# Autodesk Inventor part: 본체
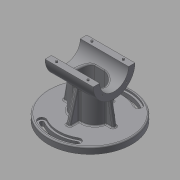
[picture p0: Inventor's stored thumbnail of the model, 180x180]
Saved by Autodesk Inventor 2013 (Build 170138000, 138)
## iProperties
Created: 2015-12
Part Number: 본체
Material: 일반
Document SubType Name: Modeling
Designer: mduedu
Density: 2.71 g/cm^3
Author: mduedu
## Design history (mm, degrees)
sketch "스케치1"
  geometry: C1 r 65 at (0, 0); 1 further point
  constraints: 1 centre point, 1 coincident
  dimensions: "d124" = 130 diameter of C1
extrude "돌출1" new body sketch "스케치1" distance "d3" = 10; taper "d4" = 0 deg
sketch "스케치2"
  geometry: C1 r 32.5 at (80, 0); 1 further point
  constraints: 1 centre point, 1 horizontal alignment
  dimensions: "d5" = 65 diameter of C1; "d125" = 80 distance of C1.centre point (0, 0)
extrude "돌출2" join sketch "스케치2" stored distance "d7" = 75; taper "d8" = 0 deg
sketch "스케치3"
  geometry: L1 (-27.5, -20)-(27.5, -20); L2 (27.5, -20)-(27.5, 20); L3 (27.5, 20)-(-27.5, 20); L4 (-27.5, 20)-(-27.5, -20); L5 (-27.5, -20)-(27.5, 20); L6 (27.5, -20)-(-27.5, 20); 1 further point
  constraints: 12 end point, 2 midpoint, 2 parallel, 1 horizontal, 1 perpendicular
  dimensions: "d9" = 55 distance of L2.end L3.end; "d11" = 40 distance of L1.end L2.end
extrude "돌출3" new body sketch "스케치3" stored distance "d12" = 75; taper "d13" = 0 deg
fillet "모깎기1"
fillet "모깎기2"
feature "결합1"
  node "솔리드2"
sketch "스케치4"
  geometry: L1 (-37.5, 47.5)-(37.5, 47.5) reference; L2 (32.5, 47.5)-(39.112, 10); L3 (37.5, 47.5)-(37.5, 112.5) reference; L4 (65, 10)-(-65, 10) reference; 1 further point
  constraints: 2 end point, 2 point on line
  dimensions: "d15" = 5 distance from line of L2.start L3; "d126" = 80 deg angle of L2 L1
sketch "스케치5"
  geometry: L1 (10, 35)-(56.569, 22.522); L2 (10, -65)-(10, 65) reference; L3 (10, 20)-(54.383, 20) reference; A1 r 32.5 centre (80, 0) between (56.569, 22.522) and (54.383, 20) reference; 1 further point
  constraints: 2 end point, 1 point on circle, 1 point on line
  dimensions: "d127" = 75 deg angle of L1 L2; "d128" = 15 distance of L1.start L3.start
feature "리브1" dims "d19" = 1, "d20" = 6, "d21" = 0, "d22" = 0, "d23" = 1, "d24" = 1
feature "리브2" dims "d25" = 1, "d26" = 6, "d27" = 0, "d28" = 0, "d29" = 1, "d30" = 1
fillet "모깎기4" dims "d31" = 2
fillet "모깎기5" dims "d32" = 2
fillet "모깎기6" dims "d33" = 2
fillet "모깎기7" dims "d41" = 2
hole "구멍2" diameter "d44" = 45; stored, may be unused: countersink angle "d48" = 90 deg, drill point angle "d50" = 118 deg; dims "d42" = 10, "d43" = 10, "d45" = 6, "d46" = 4, "d47" = 2, "d49" = 8
sketch "스케치7" dims "d52" = 26.5
  geometry: L1 (0, 0)-(32.5, 0); L2 (0, 0)-(22.981, 22.981); A1 r 32.5 centre (0, 0) between (32.5, 0) and (22.981, 22.981) reference; 3 further points
  constraints: 4 end point, 2 point on circle, 1 coincident, 1 horizontal, 1 point on line, 3 other
  dimensions: "d51" = 45 deg angle of L2 L1
hole "구멍3" sketch "스케치7" at (18.738, 18.738) diameter "d54" = 2.459; stored, may be unused: countersink angle "d58" = 90 deg, drill point angle "d60" = 118 deg; dims "d55" = 8, "d56" = 4, "d57" = 2, "d59" = 10
sketch "스케치9"
  geometry: L1 (-75, 82.5)-(75, 82.5); L2 (75, 82.5)-(75, 0); L3 (75, 0)-(-75, 0); L4 (-75, 0)-(-75, 82.5); C1 r 32.5 at (0, 0) reference; 2 further points
  constraints: 8 end point, 2 parallel, 1 coincident, 1 horizontal, 1 midpoint, 1 perpendicular
  dimensions: "d71" = 50 distance edge to line of C1 L1; "d116" = 150 distance between parallel lines of L2 L4
extrude "돌출5" cut sketch "스케치9" stored distance "d73" = 0; taper "d74" = 0 deg
node "작업 평면1"
sketch "스케치10"
  geometry: L1 (-7.5, 15)-(7.5, 15); L2 (-7.5, -15)-(7.5, -15); A1 r 20 centre (-7.5, 0) between (-7.5, 20) and (-26.977, 4.545) reference; A2 r 20 centre (7.5, 0) between (26.977, 4.545) and (7.5, 20) reference; A3 r 15 centre (-7.5, 0) between (-7.5, 15) and (-7.5, -15); A4 r 15 centre (7.5, 0) between (7.5, -15) and (7.5, 15); 1 further point
  constraints: 7 point on circle, 4 end point, 4 tangent, 3 point on line, 2 centre point, 2 coincident, 1 horizontal
  dimensions: "d77" = 5 radial gap between concentric circles of A3 A1
extrude "돌출6" cut sketch "스케치10" stored distance "d78" = 50; taper "d79" = 0 deg
fillet "모깎기10" dims "d80" = 3
sketch "스케치11"
  geometry: 2 further points
  constraints: 1 coincident
hole "구멍4" sketch "스케치11" at (0, 0) diameter "d81" = 12; stored, may be unused: countersink angle "d85" = 90 deg, drill point angle "d87" = 118 deg; dims "d82" = 8, "d83" = 40, "d84" = 10, "d86" = 10
sketch "스케치12"
  geometry: C1 r 10 at (0, 0); 1 further point
  constraints: 1 centre point, 1 coincident
  dimensions: "d88" = 20 diameter of C1
extrude "돌출7" cut sketch "스케치12" distance "d89" = 5; taper "d90" = 0 deg
chamfer "모따기1" distance "d91" = 1; stored, may be unused: second distance "d92" = 2, angle "d93" = 45 deg
fillet "모깎기11" dims "d94" = 0.5
fillet "모깎기12" dims "d115" = 0.3
sketch "스케치15"
  geometry: L1 (-75, 55)-(-75, 65) reference; L2 (0, 65)-(0, 55) reference; L3 (-75, 60)-(0, 60); C1 r 1.5 at (-62, 60); 1 further point
  constraints: 2 end point, 2 midpoint, 1 centre point, 1 point on line
  dimensions: "d117" = 3 diameter of C1; "d118" = 13 distance from line of C1.centre L1
extrude "돌출8" join sketch "스케치15" distance "d119" = 1.8; taper "d120" = 0 deg
chamfer "모따기2" distance "d121" = 0.5; stored, may be unused: second distance "d122" = 2, angle "d123" = 45 deg
sketch "스케치16"
  geometry: L1 (0, 0)-(61, 0); L2 (0, 0)-(30.5, 52.828); L3 (0, 0)-(-30.5, 52.828); L4 (0, 0)-(-61, 0); A1 r 55 centre (0, 0) between (-27.5, 47.631) and (27.5, 47.631); A2 r 61 centre (0, 0) between (-30.5, 52.828) and (30.5, 52.828); A3 r 49 centre (0, 0) between (-24.5, 42.435) and (24.5, 42.435); A4 r 6 centre (-27.5, 47.631) between (-30.5, 52.828) and (-24.5, 42.435); A5 r 6 centre (27.5, 47.631) between (30.5, 52.828) and (24.5, 42.435); A6 r 49 centre (0, 0) between (24.5, 42.435) and (-24.5, 42.435); A7 r 61 centre (0, 0) between (30.5, 52.828) and (-30.5, 52.828); 1 further point
  constraints: 15 point on circle, 8 end point, 7 centre point, 2 point on line, 1 coincident, 1 horizontal, 10 other
  dimensions: "d129" = 110 diameter of A1; "d130" = 6 radial gap between concentric circles of A1 A2; "d131" = 6 radial gap between concentric circles of A3 A1; "d134" = 180 deg dimension on point (0, 0) L1.end L4.end
extrude "돌출9" cut sketch "스케치16" distance "d136" = 3; taper "d137" = 0 deg
sketch "스케치17"
  geometry: A1 r 6 centre (27.5, 47.631) between (24.5, 42.435) and (30.5, 52.828) reference; A2 r 61 centre (0, 0) between (30.5, 52.828) and (-30.5, 52.828) reference; A3 r 6 centre (-27.5, 47.631) between (-30.5, 52.828) and (-24.5, 42.435) reference; A4 r 49 centre (0, 0) between (24.5, 42.435) and (-24.5, 42.435) reference; A5 r 58 centre (0, 0) between (29, 50.229) and (-29, 50.229); A6 r 3 centre (27.5, 47.631) between (26, 45.033) and (29, 50.229); A7 r 52 centre (0, 0) between (26, 45.033) and (-26, 45.033); A8 r 3 centre (-27.5, 47.631) between (-29, 50.229) and (-26, 45.033); 1 further point
  constraints: 8 point on circle, 4 centre point, 3 other
  dimensions: "d138" = 3 radial gap between concentric circles of A5 A2
extrude "돌출10" cut sketch "스케치17" stored distance "d139" = 3; taper "d140" = 0 deg
node "솔리드1"
mirror "대칭1"
mirror "대칭2"
pattern_circular "원형 패턴1" dims angle "d62" = 360 deg
mirror "대칭3"
mirror "대칭5"
mirror "대칭6"
mirror "대칭7"
node "투영된 루프1"
